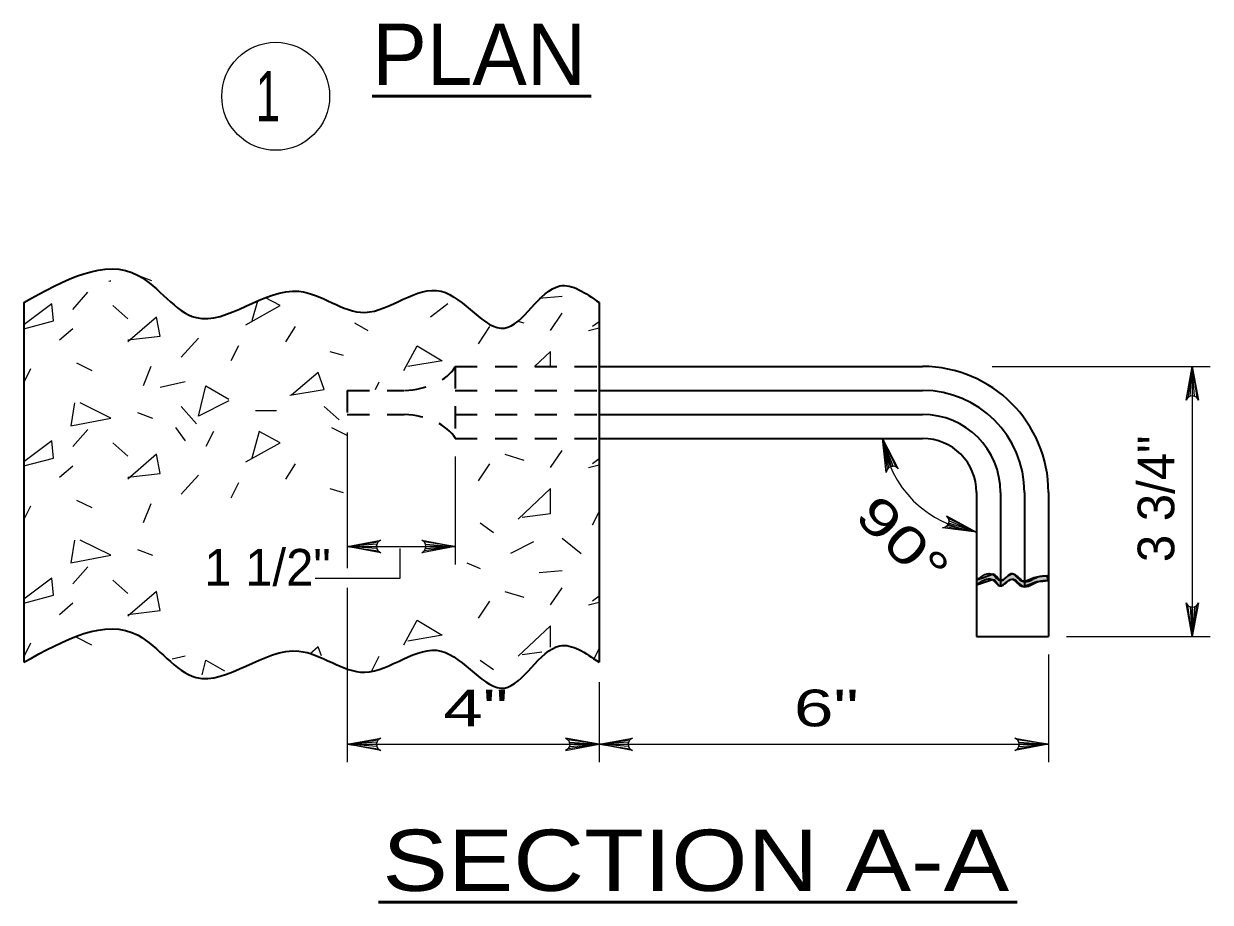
# Model space of a CAD drawing. Extents: x 16 to 133, y -56 to 112.
# Drawn here: x 23.65 to 56.65, y 40.02 to 64.43 of the extents above; entities that cross this region are included whole.
import ezdxf
from ezdxf.enums import TextEntityAlignment as Align

# ---------------------------------------------------------------- set-up
doc = ezdxf.new("R2010")
doc.units = 0
doc.header["$LTSCALE"] = 0.41
doc.linetypes.add('SHORT_DASHED', pattern=[2.7, 1.5, -1.2])
for name, color, linetype, lineweight in [('1', 7, 'Continuous', 35), ('10', 7, 'Continuous', 13), ('12', 7, 'Continuous', 53), ('13', 7, 'Continuous', 25), ('6', 7, 'Continuous', 13)]:
    doc.layers.add(name, color=color, linetype=linetype, lineweight=lineweight)

msp = doc.modelspace()

# ---------------------------------------------------------------- hatches: boundary and pattern name
at = {"layer": '1'}
msp.add_hatch(color=256, dxfattribs=at).paths.add_polyline_path([(50.1468, 48.8324), (50.5587, 48.9778), (50.5919, 48.9878), (50.6417, 48.9712), (50.6815, 48.928), (50.738, 48.8549), (50.7645, 48.8217), (50.7944, 48.8117), (50.8243, 48.8084), (50.8575, 48.815), (50.8907, 48.8383), (50.967, 48.9014), (51.0401, 48.9579), (51.0899, 48.9878), (51.1297, 48.9977), (51.1696, 48.9878), (51.226, 48.9446), (51.2791, 48.8914), (51.3389, 48.8283), (51.3721, 48.815), (51.402, 48.7951), (51.4551, 48.7918), (51.5016, 48.8084), (51.6111, 48.8483), (51.7639, 48.9114), (51.8203, 48.9247), (51.8834, 48.9313), (51.9929, 48.9413), (52.1423, 48.9612), (52.112, 49.0845), (51.8302, 49.0509), (51.7406, 49.0309), (51.6344, 48.9878), (51.5149, 48.9413), (51.4551, 48.9346), (51.402, 48.9379), (51.3588, 48.9645), (51.2692, 49.0476), (51.1995, 49.114), (51.1496, 49.1406), (51.0965, 49.1406), (51.0301, 49.0974), (50.9405, 49.0243), (50.8807, 48.9778), (50.8276, 48.9579), (50.7911, 48.9678), (50.7546, 49.0011), (50.7015, 49.0675), (50.6516, 49.1107), (50.6118, 49.1306), (50.5355, 49.1007), (50.3429, 49.0343), (50.1468, 48.9656)])

# ---------------------------------------------------------------- linework, layer by layer
for p, q in [((23.6468, 56.6833), (23.6468, 46.6833)), ((39.6468, 56.6833), (39.6468, 46.6833)), ((39.6468, 54.9043), (48.6468, 54.9043)), ((39.6468, 54.2376), (48.6468, 54.2376)), ((39.6468, 53.5709), (48.6468, 53.5709)), ((39.6468, 52.9043), (48.6468, 52.9043)), ((50.1468, 51.4043), (50.1468, 47.4043)), ((50.8135, 51.4043), (50.8135, 48.8053)), ((51.4801, 51.4043), (51.4801, 48.8031)), ((52.1468, 51.4043), (52.1468, 47.4043)), ((50.1468, 47.4043), (52.1468, 47.4043))]:
    msp.add_line(p, q, dxfattribs=at)
at = {"layer": '1', "linetype": 'SHORT_DASHED'}
for p, q in [((35.6468, 54.9043), (39.6468, 54.9043)), ((35.6468, 54.9043), (35.6468, 52.9043)), ((32.6468, 54.2376), (32.6468, 53.5709)), ((32.6468, 54.2376), (34.2149, 54.2376)), ((35.6468, 54.2376), (39.6468, 54.2376)), ((32.6468, 53.5709), (34.2231, 53.5709)), ((35.6468, 53.5709), (39.6468, 53.5709)), ((35.6468, 52.9043), (39.6468, 52.9043))]:
    msp.add_line(p, q, dxfattribs=at)
at = {"layer": '1'}
msp.add_lwpolyline([(50.1468, 48.8324), (50.5587, 48.9778), (50.5919, 48.9878), (50.6417, 48.9712), (50.6815, 48.928), (50.738, 48.8549), (50.7645, 48.8217), (50.7944, 48.8117), (50.8243, 48.8084), (50.8575, 48.815), (50.8907, 48.8383), (50.967, 48.9014), (51.0401, 48.9579), (51.0899, 48.9878), (51.1297, 48.9977), (51.1696, 48.9878), (51.226, 48.9446), (51.2791, 48.8914), (51.3389, 48.8283), (51.3721, 48.815), (51.402, 48.7951), (51.4551, 48.7918), (51.5016, 48.8084), (51.6111, 48.8483), (51.7639, 48.9114), (51.8203, 48.9247), (51.8834, 48.9313), (51.9929, 48.9413), (52.1423, 48.9612), (52.112, 49.0845), (51.8302, 49.0509), (51.7406, 49.0309), (51.6344, 48.9878), (51.5149, 48.9413), (51.4551, 48.9346), (51.402, 48.9379), (51.3588, 48.9645), (51.2692, 49.0476), (51.1995, 49.114), (51.1496, 49.1406), (51.0965, 49.1406), (51.0301, 49.0974), (50.9405, 49.0243), (50.8807, 48.9778), (50.8276, 48.9579), (50.7911, 48.9678), (50.7546, 49.0011), (50.7015, 49.0675), (50.6516, 49.1107), (50.6118, 49.1306), (50.5355, 49.1007), (50.3429, 49.0343), (50.1468, 48.9656)], close=True, dxfattribs=at)
for radius in [3.5, 2.8333, 2.1667, 1.5]:
    msp.add_arc((48.6468, 51.4043), radius, 0, 90, dxfattribs=at)
at = {"layer": '1', "linetype": 'SHORT_DASHED'}
for centre, major_axis, start_param, end_param in [((34.1035, 55.2848), (-1.6532, 0.0275), 1.6623654, 2.7852821), ((34.1007, 52.5241), (1.6532, 0.0275), 0.3446976, 1.4792273)]:
    msp.add_ellipse(centre, major_axis=major_axis, ratio=0.634051, start_param=start_param, end_param=end_param, dxfattribs=at)
at = {"layer": '1'}
for points in [[(23.6468, 56.6833), (26.83, 57.4348), (28.4422, 56.2616), (31.3002, 56.9948), (33.1323, 56.4082), (35.2575, 56.9948), (37.0162, 55.9683), (38.5552, 57.1415), (39.6468, 56.6833)], [(50.1437, 48.9645), (50.5973, 49.1241), (50.8133, 48.956), (51.1376, 49.1432), (51.4565, 48.9305), (51.8434, 49.0558), (52.139, 49.0874)], [(50.143, 48.8311), (50.5745, 48.9834), (50.8029, 48.8057), (51.1329, 48.9961), (51.4374, 48.793), (51.8689, 48.9327), (52.1354, 48.9581)], [(23.6468, 46.6833), (26.83, 47.4348), (28.4422, 46.2616), (31.3002, 46.9948), (33.1323, 46.4082), (35.2575, 46.9948), (37.0162, 45.9683), (38.5552, 47.1415), (39.6468, 46.6833)]]:
    msp.add_spline(points, degree=3, dxfattribs=at)
at = {"layer": '10'}
for p, q in [((50.5833, 54.9043), (56.6468, 54.9043)), ((56.1468, 54.9043), (56.1468, 47.4043)), ((32.6468, 53.0709), (32.6468, 49.2978)), ((35.6468, 52.4043), (35.6468, 49.4043)), ((32.6468, 49.9043), (35.6468, 49.9043)), ((32.6468, 48.7485), (32.6468, 43.9043)), ((52.6468, 47.4043), (56.6468, 47.4043)), ((52.1468, 46.9043), (52.1468, 43.9043)), ((39.6468, 46.1336), (39.6468, 43.9043))]:
    msp.add_line(p, q, dxfattribs=at)
for points in [[(56.1468, 54.9043), (56.3215, 53.9722), (56.2718, 54.044), (56.2093, 54.081), (56.1468, 54.0918), (56.0843, 54.081), (56.0218, 54.044), (55.972, 53.9722), (56.1468, 54.9043), (56.0218, 54.044), (56.0843, 54.081), (56.1468, 54.9043), (56.1468, 54.0918), (56.2093, 54.081), (56.1468, 54.9043), (56.2718, 54.044)], [(47.5295, 52.9016), (47.9698, 52.0617), (47.9012, 52.1158), (47.8306, 52.1329), (47.7677, 52.1248), (47.7111, 52.0962), (47.6622, 52.0425), (47.6357, 51.9592), (47.5295, 52.9016), (47.6622, 52.0425), (47.7111, 52.0962), (47.5295, 52.9016), (47.7677, 52.1248), (47.8306, 52.1329), (47.5295, 52.9016), (47.9012, 52.1158)], [(50.1436, 50.2955), (49.2036, 50.4203), (49.2873, 50.4452), (49.342, 50.493), (49.3717, 50.5491), (49.381, 50.6118), (49.3653, 50.6827), (49.3126, 50.7524), (50.1436, 50.2955), (49.3653, 50.6827), (49.381, 50.6118), (50.1436, 50.2955), (49.3717, 50.5491), (49.342, 50.493), (50.1436, 50.2955), (49.2873, 50.4452)], [(31.7532, 49.0178), (34.1117, 49.0178), (34.1117, 49.8481)], [(32.6468, 49.9043), (33.5789, 50.079), (33.507, 50.0293), (33.47, 49.9668), (33.4593, 49.9043), (33.47, 49.8418), (33.507, 49.7793), (33.5789, 49.7295), (32.6468, 49.9043), (33.507, 49.7793), (33.47, 49.8418), (32.6468, 49.9043), (33.4593, 49.9043), (33.47, 49.9668), (32.6468, 49.9043), (33.507, 50.0293)], [(35.6468, 49.9043), (34.7147, 49.7295), (34.7865, 49.7793), (34.8236, 49.8418), (34.8343, 49.9043), (34.8236, 49.9668), (34.7865, 50.0293), (34.7147, 50.079), (35.6468, 49.9043), (34.7865, 50.0293), (34.8236, 49.9668), (35.6468, 49.9043), (34.8343, 49.9043), (34.8236, 49.8418), (35.6468, 49.9043), (34.7865, 49.7793)], [(56.1468, 47.4043), (55.972, 48.3363), (56.0218, 48.2645), (56.0843, 48.2275), (56.1468, 48.2168), (56.2093, 48.2275), (56.2718, 48.2645), (56.3215, 48.3363), (56.1468, 47.4043), (56.2718, 48.2645), (56.2093, 48.2275), (56.1468, 47.4043), (56.1468, 48.2168), (56.0843, 48.2275), (56.1468, 47.4043), (56.0218, 48.2645)], [(32.6468, 44.4043), (33.5789, 44.579), (33.507, 44.5293), (33.47, 44.4668), (33.4593, 44.4043), (33.47, 44.3418), (33.507, 44.2793), (33.5789, 44.2295), (32.6468, 44.4043), (33.507, 44.2793), (33.47, 44.3418), (32.6468, 44.4043), (33.4593, 44.4043), (33.47, 44.4668), (32.6468, 44.4043), (33.507, 44.5293)], [(32.6468, 44.4043), (33.5789, 44.579), (33.507, 44.5293), (33.47, 44.4668), (33.4593, 44.4043), (33.47, 44.3418), (33.507, 44.2793), (33.5789, 44.2295), (32.6468, 44.4043), (33.507, 44.2793), (33.47, 44.3418), (32.6468, 44.4043), (33.4593, 44.4043), (33.47, 44.4668), (32.6468, 44.4043), (33.507, 44.5293)], [(39.6468, 44.4043), (38.7147, 44.579), (38.7865, 44.5293), (38.8236, 44.4668), (38.8343, 44.4043), (38.8236, 44.3418), (38.7865, 44.2793), (38.7147, 44.2295), (39.6468, 44.4043), (38.7865, 44.2793), (38.8236, 44.3418), (39.6468, 44.4043), (38.8343, 44.4043), (38.8236, 44.4668), (39.6468, 44.4043), (38.7865, 44.5293)], [(39.6468, 44.4043), (40.5789, 44.579), (40.507, 44.5293), (40.47, 44.4668), (40.4593, 44.4043), (40.47, 44.3418), (40.507, 44.2793), (40.5789, 44.2295), (39.6468, 44.4043), (40.507, 44.2793), (40.47, 44.3418), (39.6468, 44.4043), (40.4593, 44.4043), (40.47, 44.4668), (39.6468, 44.4043), (40.507, 44.5293)], [(52.1468, 44.4043), (51.2147, 44.2295), (51.2865, 44.2793), (51.3236, 44.3418), (51.3343, 44.4043), (51.3236, 44.4668), (51.2865, 44.5293), (51.2147, 44.579), (52.1468, 44.4043), (51.2865, 44.5293), (51.3236, 44.4668), (52.1468, 44.4043), (51.3343, 44.4043), (51.3236, 44.3418), (52.1468, 44.4043), (51.2865, 44.2793)], [(32.6468, 44.4043), (39.6468, 44.4043), (52.1468, 44.4043)]]:
    msp.add_lwpolyline(points, dxfattribs=at)
msp.add_arc((50.5055, 53.2998), 3, 187.57536, 263.13275, dxfattribs=at)
at = {"layer": '12'}
for p, q in [((33.3419, 62.4121), (39.4296, 62.4121)), ((33.518, 40.0157), (51.2756, 40.0157))]:
    msp.add_line(p, q, dxfattribs=at)
at = {"layer": '13'}
msp.add_circle((30.654, 62.4121), 1.5, dxfattribs=at)
at = {"layer": '6'}
for p, q in [((26.8091, 57.4416), (27.2023, 57.2941)), ((26.0121, 57.2721), (26.0121, 57.2721)), ((26.0121, 57.2721), (26.0121, 57.2721)), ((25.0088, 56.4884), (25.4324, 56.965)), ((37.9819, 56.8061), (38.6173, 56.8591)), ((26.1208, 56.5943), (26.5444, 56.2237)), ((30.1439, 56.7225), (29.9862, 56.1707)), ((35.4402, 56.6473), (34.9636, 56.2766)), ((32.8456, 56.1178), (33.2163, 55.906)), ((37.3907, 56.168), (37.5583, 56.1178)), ((38.2996, 55.906), (38.6173, 56.3825)), ((39.6468, 56.1486), (39.4645, 56.0119)), ((24.6381, 55.6412), (25.0088, 55.9589)), ((30.9393, 55.5883), (31.2041, 56.0119)), ((36.6051, 56.0119), (36.2874, 55.5353)), ((39.3586, 55.906), (39.6468, 55.9818)), ((28.5036, 55.6942), (28.027, 55.1646)), ((29.6156, 55.4823), (29.4037, 55.0587)), ((32.1572, 55.3235), (32.5279, 55.2176)), ((23.6468, 54.4528), (23.8439, 54.8469)), ((25.1147, 55.0058), (25.5383, 54.794)), ((27.1798, 54.8999), (26.968, 54.3704)), ((28.1329, 54.4763), (27.4446, 54.3174)), ((33.4285, 54.2654), (33.534, 54.4763)), ((26.8091, 53.6291), (27.2327, 53.4702)), ((28.027, 53.7879), (28.4506, 53.3113)), ((30.0921, 53.682), (30.6746, 53.682)), ((31.9984, 53.7879), (32.422, 53.4172)), ((25.0088, 52.6759), (25.4324, 53.1525)), ((27.8682, 53.2054), (28.1329, 52.8348)), ((32.2102, 53.2054), (32.6338, 52.9936)), ((28.9272, 53.0995), (28.7154, 52.6759)), ((26.1208, 52.7818), (26.5444, 52.4112)), ((38.2996, 52.0935), (38.6173, 52.57)), ((24.6381, 51.8287), (25.0088, 52.1464)), ((30.9393, 51.7758), (31.2041, 52.1994)), ((36.6051, 52.1994), (36.2874, 51.7228)), ((37.0288, 52.4641), (37.5583, 52.3053)), ((39.3586, 52.0935), (39.6468, 52.1693)), ((39.6468, 52.3361), (39.4645, 52.1994)), ((28.5036, 51.8817), (28.027, 51.3521)), ((29.6156, 51.6698), (29.4037, 51.2462)), ((32.1572, 51.511), (32.5279, 51.4051)), ((25.1147, 51.1933), (25.5383, 50.9815)), ((23.6468, 50.6403), (23.8439, 51.0344)), ((27.1798, 51.0874), (26.968, 50.5579)), ((39.4645, 50.5049), (39.6468, 50.8695)), ((36.3404, 50.5579), (36.711, 50.2931)), ((37.823, 50.0284), (37.1876, 49.7107)), ((38.6173, 50.1343), (39.1468, 49.7107)), ((26.8091, 49.8166), (27.2327, 49.6577)), ((25.0088, 48.8634), (25.4324, 49.34)), ((35.9697, 49.4459), (36.3404, 49.287)), ((37.9819, 49.1811), (38.6173, 49.2341)), ((26.1208, 48.9693), (26.5444, 48.5987)), ((37.0288, 48.6516), (37.5583, 48.4928)), ((38.2996, 48.281), (38.6173, 48.7575)), ((39.6468, 48.5236), (39.4645, 48.3869)), ((24.6381, 48.0162), (25.0088, 48.3339)), ((36.6051, 48.3869), (36.2874, 47.9103)), ((39.3586, 48.281), (39.6468, 48.3568)), ((23.6468, 46.8278), (23.8439, 47.2219)), ((25.1147, 47.3808), (25.5302, 47.1731)), ((37.5053, 46.9042), (38.0564, 46.9777)), ((39.4963, 46.756), (39.6468, 47.057)), ((28.1329, 46.8513), (27.7709, 46.7677)), ((33.3222, 46.4277), (33.534, 46.8513)), ((36.3404, 46.7454), (36.711, 46.4806))]:
    msp.add_line(p, q, dxfattribs=at)
for points in [[(26.0121, 57.2721), (26.0678, 57.2827), (26.0635, 57.2849)], [(29.8274, 56.0648), (30.7805, 56.5943), (30.3755, 56.8152)], [(23.6468, 55.9516), (24.4793, 56.1707), (24.4263, 56.6473), (23.6468, 56.0626)], [(26.5444, 55.6412), (27.4446, 55.7471), (27.3387, 56.2766), (26.5444, 55.5883)], [(34.2223, 54.794), (34.593, 55.4823), (35.2814, 55.0587), (34.3282, 54.8999)], [(38.2996, 54.9043), (38.2996, 55.3235), (37.8541, 54.9043)], [(31.0452, 54.1056), (31.9984, 54.2645), (31.8395, 54.741), (31.0982, 54.1056)], [(29.3508, 53.9468), (28.5036, 53.5232), (28.7154, 54.3704), (29.3508, 53.9997)], [(25.0617, 53.8938), (24.9558, 53.2584), (26.0678, 53.4702), (25.2206, 53.8938)], [(23.6468, 52.1391), (24.4793, 52.3582), (24.4263, 52.8348), (23.6468, 52.2501)], [(29.8274, 52.2523), (30.7805, 52.7818), (30.198, 53.0995), (29.9862, 52.3582)], [(26.5444, 51.8287), (27.4446, 51.9346), (27.3387, 52.4641), (26.5444, 51.7758)], [(37.5053, 50.7167), (38.2996, 50.8226), (38.2996, 51.511), (37.3994, 50.6638)], [(25.0617, 50.0813), (24.9558, 49.4459), (26.0678, 49.6577), (25.2206, 50.0813)], [(23.6468, 48.3266), (24.4793, 48.5457), (24.4263, 49.0223), (23.6468, 48.4376)], [(26.5444, 48.0162), (27.4446, 48.1221), (27.3387, 48.6516), (26.5444, 47.9633)], [(34.2223, 47.169), (34.593, 47.8573), (35.2814, 47.4337), (34.3282, 47.2749)], [(38.2996, 47.1045), (38.2996, 47.6985), (37.3994, 46.8513)], [(31.925, 46.8596), (31.8395, 47.116), (31.6002, 46.9109)], [(28.6137, 46.3385), (28.7154, 46.7454), (29.2329, 46.4435)]]:
    msp.add_lwpolyline(points, dxfattribs=at)

# ---------------------------------------------------------------- texts
at = {"layer": '12'}
msp.add_text('PLAN', height=1.7, dxfattribs=at).set_placement((36.311, 62.7283), align=Align.CENTER)
at = {"layer": '12', "width": 1.2}
msp.add_text('SECTION A-A', height=1.7, dxfattribs=at).set_placement((42.337, 40.3319), align=Align.CENTER)
at = {"layer": '13'}
for s, height, width, p in [('1', 1.4, 0.65, (30.4402, 61.7121)), ('4"', 1.02, 1.45, (36.2185, 44.9043)), ('6"', 1.02, 1.45, (45.9685, 44.9043))]:
    msp.add_text(s, height=height, dxfattribs=dict(at, width=width)).set_placement(p, align=Align.CENTER)
msp.add_text('3 3/4"', height=1.02, rotation=90, dxfattribs=at).set_placement((55.6468, 51.2259), align=Align.CENTER)
at = {"layer": '13', "width": 1.4}
msp.add_text('90°', height=1.02, rotation=315.354, dxfattribs=at).set_placement((47.7386, 49.6796), align=Align.CENTER)
at = {"layer": '13'}
msp.add_text('1 1/2"', height=1.02, dxfattribs=at).set_placement((30.4273, 48.8137), align=Align.CENTER)

doc.saveas('drawing.dxf')
